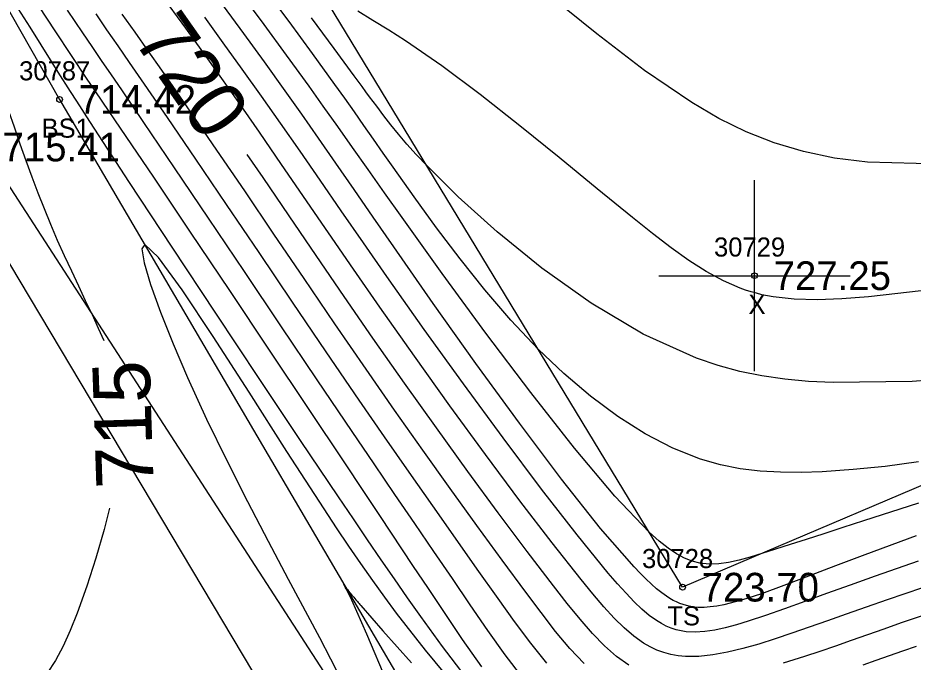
# Model space of a CAD drawing. Extents: x 1376587 to 1378239, y 1000335 to 1003031.
# Drawn here: x 1377178.89 to 1377225.72, y 1001969.67 to 1002003.38 of the extents above; entities that cross this region are included whole.
import ezdxf

# ---------------------------------------------------------------- set-up
doc = ezdxf.new("R2010")
doc.units = 0
for name, color, linetype in [('RD_DTM_BkLn2', 7, 'Continuous'), ('RD_DTM_BkLn_txCode', 7, 'Continuous'), ('RD_DTM_Major1', 7, 'Continuous'), ('RD_DTM_Major1_Lbl', 7, 'Continuous'), ('RD_DTM_Minor1', 7, 'Continuous'), ('RD_EX_Misc', 7, 'Continuous'), ('RD_EX_Misc_txCode', 7, 'Continuous'), ('RD_EX_Road', 7, 'Continuous'), ('RD_EX_TX_Misc_ELEV', 7, 'Continuous'), ('RD_SMD_Locator', 7, 'Continuous')]:
    doc.layers.add(name, color=color, linetype=linetype)

msp = doc.modelspace()

# ---------------------------------------------------------------- linework, layer by layer
at = {"layer": 'RD_DTM_BkLn2'}
for points in [[(1377334.808, 1002026.055), (1377284.229, 1002013.339), (1377249.257, 1001988.727), (1377213.659, 1001973.589), (1377188.957, 1002014.33), (1377158.44, 1002070.963), (1377139.047, 1002104.941), (1377113.892, 1002149.475), (1377071.66, 1002218.399), (1377041.895, 1002260.076), (1377023.693, 1002288.088), (1377010.927, 1002302.495), (1376992.725, 1002332.02), (1376976.352, 1002351.559)], [(1376977.592, 1002343.743), (1376991.525, 1002318.779), (1377012.226, 1002283.102), (1377032.893, 1002247.364), (1377053.281, 1002213.6), (1377075.695, 1002176.413), (1377096.747, 1002142.056), (1377117.513, 1002106.979), (1377138.493, 1002071.226), (1377160.243, 1002035.712), (1377181.074, 1001999.107), (1377204.311, 1001959.476)], [(1376971.766, 1002339.684), (1376984.16, 1002314.581), (1377005.368, 1002280.112), (1377027.082, 1002243.848), (1377048.279, 1002210.776), (1377069.87, 1002173.423), (1377092.065, 1002138.92), (1377112.017, 1002104.252), (1377133.641, 1002068.495), (1377155.53, 1002032.726), (1377177.087, 1001996.618), (1377201.678, 1001958.67), (1377205.328, 1001957.618)]]:
    msp.add_lwpolyline(points, dxfattribs=at)
at = {"layer": 'RD_DTM_Major1'}
for points in [[(1377226.008, 1001980.141), (1377224.258, 1001979.908), (1377222.578, 1001979.739), (1377220.967, 1001979.632), (1377219.857, 1001979.596), (1377218.776, 1001979.602), (1377217.717, 1001979.662), (1377216.674, 1001979.789), (1377215.639, 1001979.993), (1377214.605, 1001980.287), (1377213.156, 1001980.861), (1377211.706, 1001981.614), (1377210.266, 1001982.527), (1377208.845, 1001983.584), (1377207.454, 1001984.764), (1377206.103, 1001986.051), (1377204.68, 1001987.558), (1377203.318, 1001989.14), (1377202.02, 1001990.763), (1377200.785, 1001992.397), (1377199.616, 1001994.01), (1377198.514, 1001995.57), (1377197.999, 1001996.306), (1377197.494, 1001997.027), (1377196.995, 1001997.741), (1377196.496, 1001998.452), (1377195.99, 1001999.167), (1377195.474, 1001999.892), (1377194.302, 1002001.511), (1377193.073, 1002003.186), (1377191.81, 1002004.896)], [(1377202.281, 1001968.94), (1377201.103, 1001970.479), (1377199.966, 1001972.054), (1377199.277, 1001973.032), (1377198.59, 1001974.018), (1377197.896, 1001975.026), (1377197.184, 1001976.069), (1377196.444, 1001977.16), (1377195.666, 1001978.314), (1377193.68, 1001981.267), (1377191.511, 1001984.508), (1377189.241, 1001987.918), (1377186.954, 1001991.376), (1377184.733, 1001994.762), (1377182.659, 1001997.956), (1377181.98, 1001999.012), (1377181.65, 1001999.528), (1377181.005, 1002000.54), (1377180.69, 1002001.037), (1377179.526, 1002002.884), (1377178.437, 1002004.625)], [(1377176.521, 1002004.175), (1377176.928, 1002002.947), (1377177.231, 1002002.03), (1377177.53, 1002001.129), (1377177.823, 1002000.243), (1377178.114, 1001999.372), (1377178.402, 1001998.515), (1377178.689, 1001997.672), (1377178.995, 1001996.788), (1377179.303, 1001995.92), (1377179.615, 1001995.065), (1377179.933, 1001994.224), (1377180.259, 1001993.395), (1377180.596, 1001992.577), (1377180.953, 1001991.75), (1377181.318, 1001990.936), (1377181.687, 1001990.137), (1377182.055, 1001989.355), (1377182.418, 1001988.592), (1377182.769, 1001987.849), (1377183.095, 1001987.15), (1377183.385, 1001986.499)], [(1377210.846, 1001969.509), (1377210.211, 1001969.962), (1377209.582, 1001970.516), (1377208.948, 1001971.167), (1377208.298, 1001971.909), (1377207.62, 1001972.738), (1377206.905, 1001973.651), (1377205.523, 1001975.462), (1377204.019, 1001977.475), (1377202.427, 1001979.646), (1377200.782, 1001981.925), (1377199.115, 1001984.267), (1377197.462, 1001986.626), (1377195.954, 1001988.806), (1377194.49, 1001990.943), (1377193.076, 1001993.02), (1377191.716, 1001995.019), (1377190.885, 1001996.235)], [(1377183.682, 1001977.716), (1377183.402, 1001976.612), (1377182.968, 1001975.114), (1377182.491, 1001973.636), (1377181.985, 1001972.226), (1377181.63, 1001971.328), (1377181.258, 1001970.496), (1377180.859, 1001969.744), (1377180.422, 1001969.083), (1377179.936, 1001968.525), (1377179.39, 1001968.084), (1377178.768, 1001967.764)], [(1377226.605, 1001972.232), (1377225.099, 1001971.716), (1377224.195, 1001971.4), (1377223.325, 1001971.094), (1377222.48, 1001970.796), (1377221.654, 1001970.508), (1377220.84, 1001970.229), (1377220.032, 1001969.959), (1377218.928, 1001969.607)]]:
    msp.add_lwpolyline(points, dxfattribs=at)
at = {"layer": 'RD_DTM_Minor1'}
for points in [[(1377226.006, 1001977.985), (1377223.127, 1001977.06), (1377222.038, 1001976.708), (1377221.04, 1001976.387), (1377220.127, 1001976.092), (1377219.289, 1001975.823), (1377218.521, 1001975.579), (1377217.814, 1001975.356), (1377217.194, 1001975.166), (1377216.614, 1001975.004), (1377216.068, 1001974.88), (1377215.548, 1001974.806), (1377215.047, 1001974.79), (1377214.556, 1001974.843), (1377214.159, 1001974.945), (1377213.756, 1001975.106), (1377213.339, 1001975.332), (1377212.898, 1001975.629), (1377212.427, 1001976.005), (1377211.915, 1001976.465), (1377210.118, 1001978.353), (1377208.011, 1001980.855), (1377205.721, 1001983.767), (1377203.372, 1001986.885), (1377201.087, 1001990.006), (1377198.992, 1001992.927), (1377198.069, 1001994.228), (1377197.209, 1001995.447), (1377196.396, 1001996.599), (1377195.619, 1001997.7), (1377194.865, 1001998.765), (1377194.119, 1001999.809), (1377192.947, 1002001.429), (1377191.774, 1002003.031), (1377190.61, 1002004.612)], [(1377254.944, 1002004.376), (1377253.361, 1002003.256), (1377251.702, 1002002.203), (1377249.925, 1002001.215), (1377247.988, 1002000.289), (1377244.239, 1001998.847), (1377240.086, 1001997.623), (1377235.724, 1001996.663), (1377231.348, 1001996.013), (1377227.153, 1001995.718), (1377223.334, 1001995.823), (1377221.598, 1001996.044), (1377219.98, 1001996.381), (1377218.453, 1001996.837), (1377216.988, 1001997.414), (1377215.559, 1001998.116), (1377214.137, 1001998.943), (1377211.675, 1002000.628), (1377209.179, 1002002.548), (1377206.679, 1002004.562)], [(1377203.167, 1001969.421), (1377202.155, 1001970.845), (1377201.163, 1001972.315), (1377200.363, 1001973.513), (1377199.552, 1001974.73), (1377197.855, 1001977.281), (1377196.947, 1001978.647), (1377195.985, 1001980.094), (1377194.086, 1001982.946), (1377192.054, 1001985.991), (1377189.972, 1001989.105), (1377187.925, 1001992.162), (1377185.994, 1001995.036), (1377184.263, 1001997.603), (1377183.336, 1001998.971), (1377182.904, 1001999.609), (1377182.487, 1002000.225), (1377181.689, 1002001.411), (1377180.836, 1002002.692), (1377179.996, 1002003.972)], [(1377226.203, 1001973.56), (1377224.354, 1001972.927), (1377223.261, 1001972.543), (1377222.223, 1001972.175), (1377221.234, 1001971.824), (1377220.29, 1001971.492), (1377219.383, 1001971.179), (1377218.509, 1001970.887), (1377217.645, 1001970.615), (1377216.811, 1001970.376), (1377216.009, 1001970.182), (1377215.24, 1001970.041), (1377214.506, 1001969.964), (1377213.809, 1001969.962), (1377213.422, 1001969.998), (1377213.046, 1001970.065), (1377212.679, 1001970.163), (1377212.32, 1001970.294), (1377211.965, 1001970.461), (1377211.613, 1001970.664), (1377211.11, 1001971.023), (1377210.602, 1001971.46), (1377210.079, 1001971.976), (1377209.535, 1001972.569), (1377208.96, 1001973.238), (1377208.348, 1001973.985), (1377206.834, 1001975.902), (1377205.149, 1001978.112), (1377203.35, 1001980.533), (1377201.492, 1001983.083), (1377199.632, 1001985.679), (1377197.827, 1001988.24), (1377196.449, 1001990.221), (1377195.136, 1001992.127), (1377192.68, 1001995.713), (1377191.523, 1001997.393), (1377190.406, 1001998.998), (1377189.47, 1002000.323), (1377188.559, 1002001.599), (1377187.672, 1002002.833), (1377186.81, 1002004.031)], [(1377225.877, 1001976.269), (1377223.196, 1001975.288), (1377221.657, 1001974.702), (1377220.244, 1001974.158), (1377218.956, 1001973.669), (1377217.79, 1001973.249), (1377216.744, 1001972.912), (1377215.817, 1001972.671), (1377215.454, 1001972.601), (1377215.11, 1001972.553), (1377214.781, 1001972.53), (1377214.465, 1001972.533), (1377214.159, 1001972.564), (1377213.86, 1001972.626), (1377213.688, 1001972.677), (1377213.518, 1001972.74), (1377213.347, 1001972.814), (1377213.175, 1001972.9), (1377213.001, 1001972.999), (1377212.826, 1001973.111), (1377212.568, 1001973.295), (1377212.303, 1001973.507), (1377212.027, 1001973.748), (1377211.74, 1001974.018), (1377211.441, 1001974.317), (1377211.126, 1001974.647), (1377209.372, 1001976.666), (1377207.335, 1001979.234), (1377205.125, 1001982.172), (1377202.85, 1001985.299), (1377200.621, 1001988.435), (1377198.549, 1001991.399), (1377197.476, 1001992.947), (1377196.474, 1001994.398), (1377195.528, 1001995.769), (1377194.622, 1001997.076), (1377193.743, 1001998.336), (1377192.876, 1001999.565), (1377191.796, 1002001.07), (1377190.718, 1002002.552), (1377189.651, 1002004.009)], [(1377205.309, 1001968.843), (1377204.383, 1001970.041), (1377203.471, 1001971.324), (1377202.554, 1001972.664), (1377201.618, 1001974.038), (1377200.653, 1001975.452), (1377199.652, 1001976.918), (1377198.61, 1001978.446), (1377197.519, 1001980.05), (1377196.372, 1001981.741), (1377194.551, 1001984.438), (1377192.652, 1001987.26), (1377190.736, 1001990.113), (1377188.862, 1001992.901), (1377187.091, 1001995.529), (1377185.484, 1001997.902), (1377184.321, 1001999.606), (1377183.784, 1002000.392), (1377183.268, 1002001.148), (1377182.769, 1002001.881), (1377182.282, 1002002.6), (1377181.492, 1002003.781)], [(1377206.555, 1001969.617), (1377205.718, 1001970.662), (1377204.876, 1001971.796), (1377204.012, 1001973.001), (1377202.921, 1001974.535), (1377201.779, 1001976.147), (1377200.588, 1001977.837), (1377199.35, 1001979.605), (1377198.067, 1001981.45), (1377196.741, 1001983.373), (1377195.009, 1001985.91), (1377193.251, 1001988.505), (1377191.504, 1001991.095), (1377189.806, 1001993.611), (1377188.197, 1001995.99), (1377186.715, 1001998.166), (1377186.019, 1001999.177), (1377185.36, 1002000.13), (1377184.733, 1002001.036), (1377184.13, 1002001.906), (1377183.548, 1002002.751), (1377182.978, 1002003.582)], [(1377208.508, 1001969.594), (1377207.767, 1001970.385), (1377207.02, 1001971.277), (1377206.255, 1001972.26), (1377205.458, 1001973.324), (1377204.218, 1001975.006), (1377202.896, 1001976.819), (1377201.508, 1001978.745), (1377200.069, 1001980.763), (1377198.595, 1001982.856), (1377197.101, 1001985.002), (1377195.475, 1001987.368), (1377193.862, 1001989.735), (1377192.283, 1001992.065), (1377190.758, 1001994.319), (1377189.305, 1001996.457), (1377187.945, 1001998.44), (1377187.162, 1001999.567), (1377186.417, 1002000.633), (1377185.703, 1002001.649), (1377185.017, 1002002.627), (1377184.352, 1002003.577)], [(1377226.589, 1001989.155), (1377224.918, 1001988.951), (1377223.387, 1001988.786), (1377221.982, 1001988.674), (1377220.692, 1001988.626), (1377219.503, 1001988.657), (1377218.404, 1001988.778), (1377218.106, 1001988.832), (1377217.813, 1001988.893), (1377217.525, 1001988.964), (1377217.24, 1001989.044), (1377216.958, 1001989.134), (1377216.678, 1001989.234), (1377215.792, 1001989.62), (1377214.902, 1001990.104), (1377213.995, 1001990.682), (1377213.059, 1001991.348), (1377212.079, 1001992.097), (1377211.041, 1001992.924), (1377209.186, 1001994.436), (1377207.2, 1001996.066), (1377205.143, 1001997.734), (1377203.078, 1001999.363), (1377201.066, 1002000.872), (1377199.169, 1002002.183), (1377198.295, 1002002.736), (1377197.462, 1002003.242), (1377196.666, 1002003.724)], [(1377225.982, 1001974.958), (1377223.733, 1001974.172), (1377222.419, 1001973.699), (1377221.191, 1001973.251), (1377220.047, 1001972.832), (1377218.984, 1001972.448), (1377217.999, 1001972.104), (1377217.089, 1001971.803), (1377216.472, 1001971.615), (1377215.889, 1001971.458), (1377215.339, 1001971.339), (1377214.818, 1001971.262), (1377214.322, 1001971.233), (1377213.848, 1001971.257), (1377213.583, 1001971.298), (1377213.322, 1001971.36), (1377213.064, 1001971.445), (1377212.807, 1001971.552), (1377212.551, 1001971.684), (1377212.293, 1001971.842), (1377211.917, 1001972.114), (1377211.53, 1001972.441), (1377211.126, 1001972.826), (1377210.701, 1001973.267), (1377210.25, 1001973.767), (1377209.769, 1001974.326), (1377208.141, 1001976.32), (1377206.282, 1001978.718), (1377204.274, 1001981.395), (1377202.201, 1001984.224), (1377200.148, 1001987.08), (1377198.198, 1001989.837), (1377196.963, 1001991.606), (1377195.802, 1001993.282), (1377194.701, 1001994.877), (1377193.649, 1001996.4), (1377192.633, 1001997.865), (1377191.638, 1001999.281), (1377190.631, 1002000.695), (1377189.637, 1002002.073), (1377188.662, 1002003.417)], [(1377230.108, 1001984.699), (1377225.664, 1001984.349), (1377221.543, 1001984.29), (1377220.243, 1001984.355), (1377219.002, 1001984.471), (1377217.809, 1001984.645), (1377216.651, 1001984.881), (1377215.515, 1001985.187), (1377214.39, 1001985.566), (1377211.598, 1001986.832), (1377208.873, 1001988.451), (1377206.299, 1001990.283), (1377203.956, 1001992.185), (1377201.926, 1001994.017), (1377200.291, 1001995.637), (1377199.731, 1001996.232), (1377199.24, 1001996.777), (1377198.805, 1001997.287), (1377198.407, 1001997.776), (1377198.031, 1001998.259), (1377197.662, 1001998.749), (1377197.478, 1001998.996), (1377197.291, 1001999.249), (1377197.099, 1001999.51), (1377196.902, 1001999.78), (1377196.696, 1002000.061), (1377196.483, 1002000.352), (1377195.438, 1002001.771), (1377194.245, 1002003.387)], [(1377201.721, 1001968.454), (1377200.204, 1001970.285), (1377198.7, 1001972.232), (1377198.079, 1001973.074), (1377197.46, 1001973.936), (1377196.837, 1001974.823), (1377196.207, 1001975.74), (1377195.565, 1001976.693), (1377194.907, 1001977.686), (1377192.959, 1001980.696), (1377190.983, 1001983.795), (1377189.114, 1001986.704), (1377187.49, 1001989.147), (1377186.248, 1001990.845), (1377185.523, 1001991.519), (1377185.382, 1001991.286), (1377185.5, 1001990.558), (1377185.836, 1001989.426), (1377186.352, 1001987.986), (1377187.009, 1001986.33), (1377187.769, 1001984.553), (1377188.761, 1001982.386), (1377189.813, 1001980.213), (1377190.894, 1001978.07), (1377191.976, 1001975.991), (1377193.027, 1001974.01), (1377194.663, 1001970.961), (1377195.249, 1001969.844), (1377195.766, 1001968.813)], [(1377198.207, 1001968.617), (1377197.142, 1001971.135), (1377196.358, 1001972.915), (1377196.271, 1001973.098), (1377196.193, 1001973.255), (1377196.124, 1001973.388), (1377196.066, 1001973.498), (1377196.017, 1001973.586), (1377195.979, 1001973.653), (1377195.957, 1001973.689), (1377195.941, 1001973.715), (1377195.931, 1001973.731), (1377195.926, 1001973.737), (1377195.927, 1001973.734), (1377195.935, 1001973.722), (1377195.946, 1001973.705), (1377195.98, 1001973.654), (1377196.004, 1001973.621), (1377196.033, 1001973.582), (1377196.066, 1001973.538), (1377196.124, 1001973.463), (1377196.192, 1001973.378), (1377196.27, 1001973.282), (1377196.359, 1001973.176), (1377196.457, 1001973.059), (1377196.565, 1001972.932), (1377196.605, 1001972.884), (1377196.647, 1001972.836), (1377196.69, 1001972.786), (1377196.734, 1001972.735), (1377196.779, 1001972.682), (1377196.825, 1001972.629), (1377197.988, 1001971.302), (1377199.478, 1001969.622)], [(1377225.882, 1001970.484), (1377225.171, 1001970.238), (1377224.471, 1001969.994), (1377223.777, 1001969.753), (1377223.083, 1001969.514)]]:
    msp.add_lwpolyline(points, dxfattribs=at)
at = {"layer": 'RD_EX_Misc'}
for p, q in [((1377217.423, 1001984.887), (1377217.423, 1001994.887)), ((1377212.423, 1001989.887), (1377222.423, 1001989.887))]:
    msp.add_line(p, q, dxfattribs=at)
at = {"layer": 'RD_EX_Road'}
msp.add_lwpolyline([(1377350.339, 1001708.261), (1377317.923, 1001758.892), (1377286.961, 1001809.893), (1377254.767, 1001863.401), (1377224.604, 1001914.857), (1377192.26, 1001967.361), (1377160.973, 1002019.841), (1377129.715, 1002070.663), (1377099.389, 1002121.709), (1377064.159, 1002179.082), (1377033.485, 1002231.09), (1377014.7, 1002262.97), (1377013.314, 1002264.907)], dxfattribs=at)
at = {"layer": 'RD_SMD_Locator'}
for centre in [(1377181.074, 1001999.107), (1377217.423, 1001989.887), (1377213.659, 1001973.589)]:
    msp.add_circle(centre, 0.15, dxfattribs=at)

# ---------------------------------------------------------------- texts
at = {"layer": 'RD_DTM_BkLn_txCode'}
for s, p in [('30787', (1377178.956, 1002000.107)), ('BS1', (1377180.129, 1001997.107)), ('30728', (1377211.541, 1001974.589)), ('TS', (1377212.864, 1001971.589))]:
    msp.add_text(s, height=1, dxfattribs=at).set_placement(p)
at = {"layer": 'RD_DTM_Major1_Lbl'}
for s, rotation, p in [('720', 305.0285, (1377184.857, 1002002.265)), ('715', 91.9369, (1377185.999, 1001978.802))]:
    msp.add_text(s, height=3, rotation=rotation, dxfattribs=at).set_placement(p)
at = {"layer": 'RD_EX_Misc_txCode'}
for s, p in [('30729', (1377215.305, 1001990.887)), ('X', (1377217.108, 1001987.887))]:
    msp.add_text(s, height=1, dxfattribs=at).set_placement(p)
at = {"layer": 'RD_EX_TX_Misc_ELEV'}
for s, p in [('714.42', (1377182.074, 1001998.357)), ('715.41', (1377178.087, 1001995.868)), ('727.25', (1377218.423, 1001989.137)), ('723.70', (1377214.659, 1001972.839))]:
    msp.add_text(s, height=1.5, dxfattribs=at).set_placement(p)

doc.saveas('drawing.dxf')
